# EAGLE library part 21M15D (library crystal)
Monolithic Crystal Filters Source: www.vanlong.com
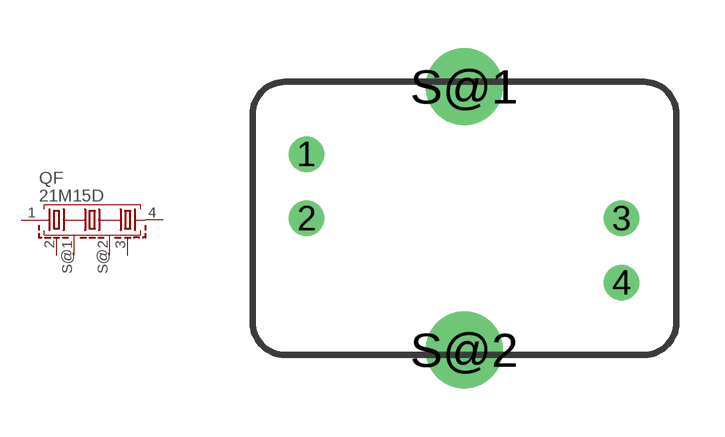
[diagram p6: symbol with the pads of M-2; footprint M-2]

Designator prefix QF

## 21M15D (OC_FARNELL: unknown; OC_NEWARK: unknown)  [M-2]
1  1  pas
2  2  pas
3  3  pas
4  4  pas
S@1  S  pas
S@2  S  pas

## Footprint M-2 (pad centres in mm)
Monolithic Crystal Filters Source: www.vanlong.com
drill 0.6 pad 1.016 round: 1 -4.9,2; 2 -4.9,0; 3 4.9,0; 4 4.9,-2
drill 1.6 pad 1.93 round: S@1 0,4.1; S@2 0,-4.1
